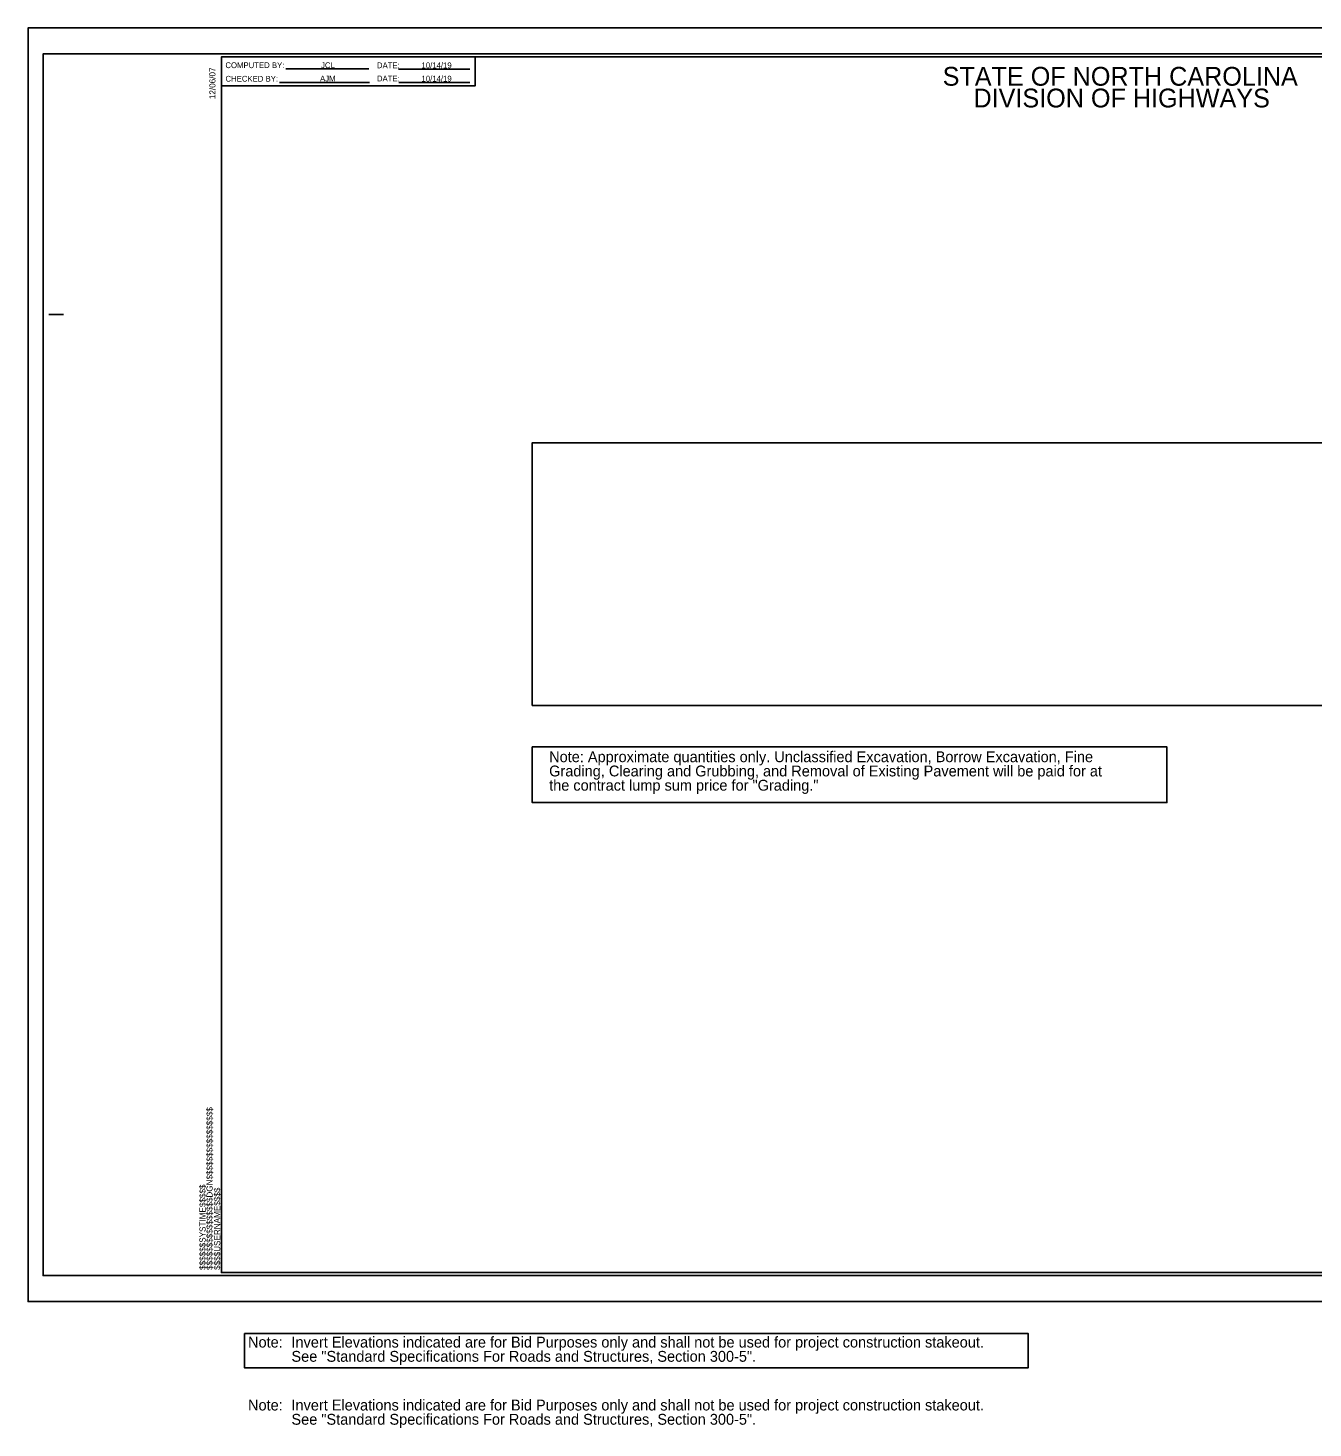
# Model space of a CAD drawing. Extents: x 406996 to 407670, y -135414 to -134930.
# Drawn here: x 406996.2 to 407440, y -135413.8 to -134930.1 of the extents above; entities that cross this region are included whole.
import ezdxf

# ---------------------------------------------------------------- set-up
doc = ezdxf.new("R2010")
doc.units = 0
for name, color, linetype in [('Default', 7, 'Continuous'), ('Prop Grid Mask', 7, 'Continuous'), ('Prop XSC Text', 7, 'Continuous'), ('Sheet Cutting Line CELL', 7, 'Continuous'), ('Sheet Data Field CELL', 7, 'Continuous'), ('Sheet Plot Border Inside CELL', 7, 'Continuous'), ('Sheet Plot Border Outside CELL', 7, 'Continuous'), ('Sheet Summary Combination CELL', 7, 'Continuous')]:
    doc.layers.add(name, color=color, linetype=linetype)

msp = doc.modelspace()

# ---------------------------------------------------------------- linework, layer by layer
at = {"layer": 'Default'}
msp.add_lwpolyline([(407170.37, -135164.13), (407567.59, -135164.13), (407567.59, -135073.41), (407170.37, -135073.41)], close=True, dxfattribs=at)
at = {"layer": 'Prop Grid Mask'}
for points in [[(407170.37, -135073.41), (407567.59, -135073.41), (407567.59, -135164.13), (407170.37, -135164.13)], [(407170.37, -135178.49), (407389.55, -135178.49), (407389.55, -135197.71), (407170.37, -135197.71)]]:
    msp.add_lwpolyline(points, close=True, dxfattribs=at)
at = {"layer": 'Prop XSC Text'}
msp.add_lwpolyline([(407070.95, -135381.14), (407341.69, -135381.14), (407341.69, -135392.96), (407070.95, -135392.96)], close=True, dxfattribs=at)
at = {"layer": 'Sheet Cutting Line CELL'}
for p, q in [((407669.8, -134930.09), (406996.2, -134930.09)), ((406996.2, -134930.09), (406996.2, -135370.09)), ((406996.2, -135370.09), (407669.8, -135370.09))]:
    msp.add_line(p, q, dxfattribs=at)
at = {"layer": 'Sheet Plot Border Inside CELL'}
msp.add_lwpolyline([(407668, -134939.07), (407001.4, -134939.07), (407001.4, -135361.11), (407668, -135361.11)], close=True, dxfattribs=at)
at = {"layer": 'Sheet Plot Border Outside CELL'}
msp.add_lwpolyline([(407669.8, -134930.09), (406996.2, -134930.09), (406996.2, -135370.09), (407669.8, -135370.09)], close=True, dxfattribs=at)
at = {"layer": 'Sheet Summary Combination CELL'}
for p, q in [((407085.26, -134944.25), (407113.88, -134944.25)), ((407124.2, -134944.31), (407148.76, -134944.31)), ((407083.08, -134948.93), (407114.16, -134948.93)), ((407124.26, -134948.91), (407148.82, -134948.91)), ((407003.44, -135029.09), (407008.44, -135029.09)), ((407063, -135360.09), (407063, -135360.09))]:
    msp.add_line(p, q, dxfattribs=at)
for points in [[(407663, -134940.09), (407063, -134940.09), (407063, -135360.09), (407663, -135360.09)], [(407063, -134940.09), (407150.6, -134940.09), (407150.6, -134950.09), (407063, -134950.09)]]:
    msp.add_lwpolyline(points, close=True, dxfattribs=at)

# ---------------------------------------------------------------- texts
at = {"layer": 'Prop XSC Text'}
for s, p in [('Note: Approximate quantities only. Unclassified Excavation, Borrow Excavation, Fine ', (407176.19, -135183.74)), ('Grading, Clearing and Grubbing, and Removal of Existing Pavement will be paid for at ', (407176.19, -135188.66)), ('the contract lump sum price for "Grading."', (407176.19, -135193.58)), ('Invert Elevations indicated are for Bid Purposes only and shall not be used for project construction stakeout.', (407087.19, -135385.97)), ('Note:', (407072.19, -135385.97)), ('See "Standard Specifications For Roads and Structures, Section 300-5".', (407087.19, -135390.89)), ('Note:', (407072.19, -135407.72)), ('Invert Elevations indicated are for Bid Purposes only and shall not be used for project construction stakeout.', (407087.19, -135407.72)), ('See "Standard Specifications For Roads and Structures, Section 300-5".', (407087.19, -135412.64))]:
    msp.add_text(s, height=3.75, dxfattribs=at).set_placement(p)
at = {"layer": 'Sheet Data Field CELL'}
for s, p in [('JCL', (407097.42, -134943.95)), ('10/14/19', (407132.11, -134943.99)), ('AJM', (407097.07, -134948.55)), ('10/14/19', (407132.11, -134948.6))]:
    msp.add_text(s, height=2, dxfattribs=at).set_placement(p)
at = {"layer": 'Sheet Summary Combination CELL'}
for s, height, p in [('COMPUTED BY:', 1.9999, (407064.38, -134943.95)), ('CHECKED BY:', 1.9999, (407064.42, -134948.63)), ('DATE:', 2, (407116.72, -134943.99)), ('DATE:', 2, (407116.72, -134948.55)), ('STATE OF NORTH CAROLINA', 6.5, (407312.1, -134950.03)), ('DIVISION OF HIGHWAYS', 6.5, (407322.74, -134957.53))]:
    msp.add_text(s, height=height, dxfattribs=at).set_placement(p)
for s, p in [('12/06/07', (407060.94, -134954.67)), ('$$$$$$$$$$$$$$$$DGN$$$$$$$$$$$$$$$$', (407059.94, -135359.15)), ('$$$$$$SYSTIME$$$$$', (407057.52, -135359.15)), ('$$$$USERNAME$$$$', (407062.57, -135359.14))]:
    msp.add_text(s, height=2.1, rotation=90, dxfattribs=at).set_placement(p)

doc.saveas('drawing.dxf')
